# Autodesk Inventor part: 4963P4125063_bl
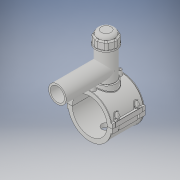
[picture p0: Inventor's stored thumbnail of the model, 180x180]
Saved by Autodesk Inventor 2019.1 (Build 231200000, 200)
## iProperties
Created: 2017-07
Part Number: 4963P4125063_bl
Material: Generic
Document SubType Name: Modeling
Designer: KIM
Density: 1 g/cm^3
Appearance: Default
Author: KIM
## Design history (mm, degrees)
derived "4963P4.ipt"
feature "Solid1::4963P4.ipt" dims "ScaleForDerivedMember" = 10
feature "Solid2::4963P4.ipt" dims "ScaleForDerivedMember" = 10
feature "Solid3::4963P4.ipt" dims "ScaleForDerivedMember" = 10
tag "TaggingFeature1"
body "Solid1"
body "Solid2"
body "Solid3"
other parameters: "d_" = 125 [user parameter], "B_" = 162 [user parameter], "L_" = 118 [user parameter], "d_t" = 6 [user parameter], "H_2" = 177 [user parameter], "H_1" = 64 [user parameter], "d_1" = 63 [user parameter], "H_" = 175 [user parameter], "d1" = 152.5 [user parameter], "d148" = 1.875 [user parameter], "d160" = 1.875 [user parameter], "d169" = 3.75 [user parameter], "d192" = 8 [user parameter], "d0" = 125 [user parameter], "d2" = 162 [user parameter], "d3" = 31.25 [user parameter], "d4" = 118 [user parameter], "d5" = 0 [user parameter], "d6" = 0.1 [user parameter], "d8" = 0 [user parameter], "d19" = 6 [user parameter], "d20" = 6 [user parameter], "d21" = 70.8 [user parameter], "d23" = 0 [user parameter], "d24" = 35.4 [user parameter], "d26" = 0 [user parameter], "d27" = 3 [user parameter], "d28" = 3 [user parameter], "d29" = 3 [user parameter], "d30" = 41.66667 [user parameter], "d31" = 6 [user parameter], "d32" = 0 [user parameter], "d33" = 0 [user parameter], "d34" = 0.6 [user parameter], "d40" = 79.3 [user parameter], "d41" = 75 [user parameter], "d43" = 0 [user parameter], "d45" = 0 [user parameter], "d47" = 147.05 [user parameter], "d70" = 15 [user parameter], "d72" = 0 [user parameter], "d73" = 6 [user parameter], "d75" = 5 [user parameter], "d76" = 0 [user parameter], "d77" = 6.25 [user parameter], "d78" = 92.5 [user parameter], "d79" = 15 [user parameter], "d80" = 47.2 [user parameter], "d82" = 5 deg [user parameter], "d84" = 4 [user parameter], "d85" = 14 [user parameter], "d86" = 0 [user parameter], "d87" = 3 [user parameter], "d88" = 0 [user parameter], "d89" = 1 [user parameter], "d90" = 1 [user parameter], "d91" = 94.4 [user parameter], "d92" = 0 [user parameter], "d93" = 0.5 [user parameter], "d94" = 65.78947 [user parameter], "d96" = 155.55 [user parameter], "d97" = 2.36 [user parameter], "d98" = 0 [user parameter], "d102" = 1.25 [user parameter], "d120" = 140 deg [user parameter], "d121" = 24.228 [user parameter], "d122" = 20 deg [user parameter], "d123" = 305 [user parameter], "d124" = 91.5 [user parameter], "d126" = 0 [user parameter], "d143" = 128.75 [user parameter], "d145" = 21.15385 [user parameter], "d149" = 1.875 [user parameter], "d150" = 23.26923 [user parameter], "d153" = 118 [user parameter], "d154" = 0 [user parameter], "d156" = 76.25 [user parameter], "d157" = 160 deg [user parameter], "d159" = 5.5 [user parameter], "d161" = 1.875 [user parameter], "d162" = 70.8 [user parameter], "d163" = 0 [user parameter], "d164" = 62.5 [user parameter], "d167" = 12.5 [user parameter], "d168" = 74.39024 [user parameter], "d170" = 3.75 [user parameter], "d172" = 0 [user parameter], "d173" = 1 [user parameter], "d175" = 62.5 [user parameter], "d176" = 20 deg [user parameter], "d177" = 8.75 [user parameter], "d178" = 27.5 [user parameter], "d180" = 0 [user parameter], "d183" = 11 [user parameter], "d184" = 7 [user parameter], "d185" = 38.35 [user parameter], "d186" = 38.35 [user parameter], "d187" = 76.25 [user parameter], "d188" = 8.25 [user parameter], "d189" = 8.75 [user parameter], "d190" = 0 [user parameter], "d191" = 114.375 [user parameter], "d193" = 8 [user parameter], "d194" = 4.13 [user parameter], "d195" = 90 deg [user parameter], "d197" = 0 [user parameter], "d199" = 0 [user parameter], "d200" = 13.75 [user parameter], "d202" = 0 [user parameter], "d203" = 177 [user parameter], "d204" = 71.25 [user parameter], "d205" = 52.5 [user parameter], "d206" = 63.75 [user parameter], "d207" = 132.75 [user parameter], "d208" = 138.06 [user parameter], "d209" = 164.61 [user parameter], "d210" = 64.5 [user parameter], "d211" = 75 [user parameter], "d213" = 29.25 [user parameter], "d216" = 0 [user parameter]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
